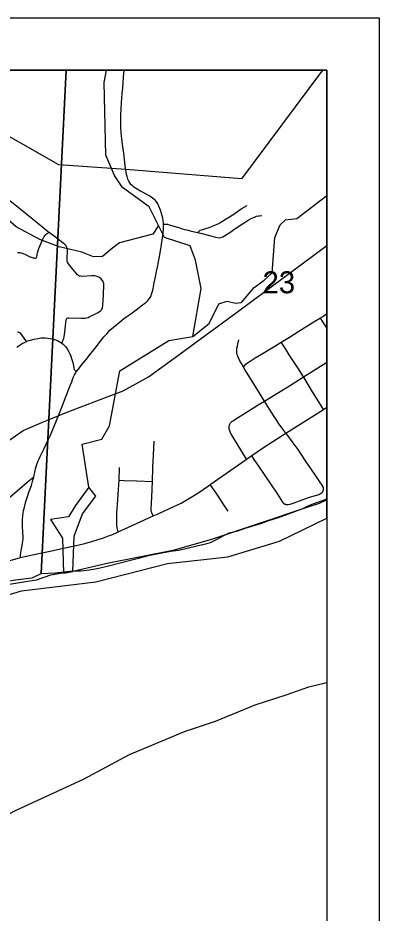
# Model space of a CAD drawing. Extents: x 0 to 34, y 0 to 22.
# Drawn here: x 8.311 to 9, y 19.29 to 21 of the extents above; entities that cross this region are included whole.
import ezdxf

# ---------------------------------------------------------------- set-up
doc = ezdxf.new("R2010")
doc.units = 0
for name, color, linetype in [('Default', 7, 'Continuous'), ('GM_X_City_Street', 7, 'Continuous'), ('GM_X_County_Road', 7, 'Continuous'), ('GM_X_Major_River', 7, 'Continuous'), ('GM_X_Minor_River', 7, 'Continuous'), ('GM_X_Rail_Line', 7, 'Continuous'), ('GM_X_Section_Text', 7, 'Continuous'), ('GM_X_State_Route', 7, 'Continuous'), ('SH_Data', 7, 'Continuous'), ('SH_Text', 7, 'Continuous')]:
    doc.layers.add(name, color=color, linetype=linetype)

msp = doc.modelspace()

# ---------------------------------------------------------------- linework, layer by layer
at = {"layer": 'Default'}
for points in [[(6.9494, 18.7612), (7.0197, 18.8208), (7.0624, 18.8705), (7.2079, 18.9977), (7.3928, 19.1502), (7.4623, 19.2086), (7.6025, 19.305), (7.8528, 19.4948), (7.9095, 19.5426), (8.0081, 19.6871), (8.1321, 19.8131), (8.2273, 19.878), (8.3177, 19.9057), (8.4594, 19.9228), (8.5959, 19.9577), (8.7115, 19.9703), (8.8098, 20.0002), (8.9, 20.0446), (8.9, 20.9), (6.3032, 20.9)], [(8.2273, 19.878), (8.3177, 19.9057), (8.4594, 19.9228), (8.5959, 19.9577), (8.7115, 19.9703), (8.8098, 20.0002), (8.9, 20.0446), (8.9, 20.9), (8.8919, 20.9), (8.7373, 20.6926), (8.5164, 20.7102), (8.3888, 20.7195), (8.089, 20.8898)]]:
    msp.add_lwpolyline(points, dxfattribs=at)
for points in [[(8.4029, 20.9), (7.3433, 20.9), (7.2788, 19.9659), (8.2644, 19.9182), (8.275, 19.9201), (8.2864, 19.9232), (8.3061, 19.9266), (8.3212, 19.9286), (8.3379, 19.9305), (8.3553, 19.9386)], [(8.9, 20.0813), (8.9, 20.9), (8.4029, 20.9), (8.3553, 19.9386), (8.3822, 19.9402), (8.4094, 19.9433), (8.417, 19.9437), (8.4307, 19.9438), (8.4424, 19.9453), (8.4549, 19.9469), (8.4678, 19.9492), (8.4833, 19.9534), (8.5283, 19.9646), (8.5408, 19.968), (8.5624, 19.9738), (8.5791, 19.9772), (8.6022, 19.9811), (8.6173, 19.983), (8.6313, 19.9865), (8.6544, 19.9923), (8.6692, 19.9954), (8.6783, 19.998), (8.6911, 20.0045), (8.7036, 20.011), (8.7138, 20.0164), (8.7301, 20.0202), (8.7445, 20.0252), (8.757, 20.0294), (8.7759, 20.0348), (8.7895, 20.0401), (8.8062, 20.0451), (8.8221, 20.0505), (8.8391, 20.0573), (8.8531, 20.0623), (8.866, 20.0688), (8.8743, 20.0718), (8.8917, 20.078)]]:
    msp.add_lwpolyline(points, close=True, dxfattribs=at)
at = {"layer": 'GM_X_City_Street'}
for points in [[(8.2922, 20.6538), (8.3205, 20.6311), (8.328, 20.625), (8.3583, 20.6004), (8.3661, 20.5938), (8.3704, 20.5902)], [(8.6536, 20.5899), (8.6559, 20.5923), (8.6573, 20.5935), (8.6587, 20.5943), (8.6608, 20.5952), (8.6635, 20.5961), (8.6676, 20.5973), (8.6757, 20.5999), (8.682, 20.6023), (8.6878, 20.6047), (8.6939, 20.6075), (8.6997, 20.6108), (8.7227, 20.6253), (8.737, 20.6351), (8.7426, 20.6385), (8.7481, 20.6418)], [(8.5887, 20.606), (8.5911, 20.606), (8.593, 20.606), (8.5964, 20.6057), (8.5996, 20.6048), (8.6153, 20.6), (8.6194, 20.5987), (8.6241, 20.5973), (8.6289, 20.5959), (8.6331, 20.5949), (8.6396, 20.5933), (8.6536, 20.5899), (8.6568, 20.5892), (8.6618, 20.5879), (8.6791, 20.5835), (8.6875, 20.5812), (8.6916, 20.5804), (8.6946, 20.5802), (8.6976, 20.5804), (8.6998, 20.581), (8.702, 20.5818), (8.7052, 20.5835), (8.7119, 20.5879), (8.717, 20.5915), (8.7225, 20.5955), (8.7267, 20.5982), (8.7391, 20.6065), (8.7502, 20.6135), (8.7573, 20.6174), (8.7619, 20.6195), (8.766, 20.621), (8.7698, 20.6219), (8.7717, 20.6221), (8.7763, 20.6224)], [(8.3099, 20.5521), (8.3121, 20.552), (8.3144, 20.5517), (8.3165, 20.5513), (8.3193, 20.5503), (8.3279, 20.5466), (8.3324, 20.5445), (8.3381, 20.5423), (8.3397, 20.5417), (8.3411, 20.5414), (8.3428, 20.5411), (8.3443, 20.5412), (8.3453, 20.5416), (8.3461, 20.5423), (8.3466, 20.5437), (8.3471, 20.5463), (8.3476, 20.5488), (8.3481, 20.5513), (8.3508, 20.5596), (8.3544, 20.5683), (8.3572, 20.575), (8.3596, 20.5802), (8.361, 20.5827), (8.3626, 20.5847), (8.3638, 20.586), (8.3653, 20.5873), (8.3672, 20.5885), (8.3704, 20.5902)], [(8.3946, 20.3787), (8.3953, 20.3804), (8.3972, 20.3846), (8.3985, 20.3884), (8.399, 20.3907), (8.4, 20.3994), (8.4029, 20.4234), (8.4035, 20.4248), (8.4041, 20.4256), (8.4052, 20.4266), (8.4063, 20.4269), (8.4076, 20.4271), (8.4312, 20.4264), (8.4361, 20.4264), (8.4392, 20.4264), (8.4417, 20.4268), (8.4446, 20.4277), (8.4468, 20.4287), (8.4575, 20.4342), (8.464, 20.4374), (8.468, 20.4402), (8.47, 20.4422), (8.4711, 20.4438), (8.4719, 20.4454), (8.4723, 20.4471), (8.4728, 20.4494), (8.473, 20.4528), (8.4733, 20.4586), (8.4738, 20.4724), (8.4741, 20.4768), (8.4746, 20.4848), (8.4746, 20.4879), (8.4744, 20.492), (8.4739, 20.4942), (8.4731, 20.4965), (8.4719, 20.4984), (8.4694, 20.5014), (8.4673, 20.5033), (8.4653, 20.5047), (8.4632, 20.5056), (8.4598, 20.5065), (8.457, 20.507), (8.4515, 20.5071), (8.4332, 20.5061), (8.4302, 20.5064), (8.4283, 20.5068), (8.4272, 20.5074), (8.4257, 20.5084), (8.4244, 20.5095), (8.4214, 20.513), (8.415, 20.5206), (8.41, 20.5268), (8.4073, 20.5305), (8.4055, 20.5334), (8.4049, 20.5346), (8.4046, 20.5361), (8.4049, 20.5435), (8.4052, 20.5528), (8.405, 20.5578), (8.4048, 20.5595), (8.4043, 20.5618), (8.4037, 20.5632), (8.4025, 20.5649), (8.4016, 20.566), (8.4003, 20.5672), (8.3972, 20.5698), (8.3882, 20.5768), (8.3848, 20.5795), (8.3756, 20.5863), (8.3704, 20.5902)], [(8.7411, 20.3331), (8.7438, 20.3362), (8.745, 20.3377), (8.7459, 20.3386), (8.7487, 20.3409), (8.7537, 20.3444), (8.7637, 20.3506), (8.7753, 20.3575), (8.8009, 20.3728), (8.8134, 20.3803), (8.8291, 20.3903), (8.8469, 20.4016), (8.8772, 20.4206), (8.888, 20.4272), (8.8924, 20.4299), (8.8997, 20.4345), (8.9, 20.4347)], [(8.9, 20.4078), (8.8929, 20.4192), (8.888, 20.4272)], [(8.3085, 20.3706), (8.3113, 20.3729), (8.319, 20.3779), (8.3231, 20.3802), (8.3274, 20.3821), (8.329, 20.3829), (8.3347, 20.3847), (8.3414, 20.3865), (8.3488, 20.3879), (8.3547, 20.3886), (8.3585, 20.3888), (8.3624, 20.3887), (8.3675, 20.3882), (8.372, 20.3875), (8.3784, 20.3862), (8.3822, 20.3851), (8.3859, 20.3836), (8.3895, 20.3818), (8.3928, 20.38), (8.3946, 20.3787), (8.3972, 20.3767), (8.3996, 20.3743), (8.4022, 20.3715), (8.4046, 20.3681), (8.4073, 20.3633), (8.4099, 20.3584), (8.4117, 20.3538), (8.4132, 20.3494), (8.4153, 20.3419), (8.4167, 20.3352), (8.4175, 20.3309), (8.4182, 20.3284), (8.419, 20.327), (8.4203, 20.3257), (8.4221, 20.3237)], [(8.3274, 20.3821), (8.326, 20.3839), (8.316, 20.397), (8.3141, 20.3985), (8.3124, 20.3993), (8.3113, 20.3996), (8.31, 20.3998)], [(8.7411, 20.3331), (8.7373, 20.3401), (8.7339, 20.3464), (8.7312, 20.3517), (8.7303, 20.3536), (8.7298, 20.3551), (8.7293, 20.3565), (8.729, 20.3581), (8.7287, 20.3598), (8.7285, 20.3618), (8.7284, 20.3637), (8.7284, 20.3655), (8.7288, 20.3693), (8.7295, 20.3731), (8.7302, 20.3766), (8.7321, 20.385)], [(8.8938, 20.2521), (8.8881, 20.2613), (8.8731, 20.2855), (8.858, 20.3105), (8.8556, 20.3143), (8.8448, 20.3315), (8.8286, 20.3565), (8.8219, 20.3669), (8.8134, 20.3803)], [(8.7138, 20.2202), (8.7143, 20.2221), (8.7151, 20.224), (8.7165, 20.2262), (8.7183, 20.2281), (8.7197, 20.2295), (8.7214, 20.2306), (8.7244, 20.2326), (8.7449, 20.2456), (8.7532, 20.251), (8.7692, 20.2607), (8.7811, 20.268), (8.8051, 20.2828), (8.829, 20.2973), (8.8556, 20.3143), (8.8688, 20.3227), (8.9, 20.3425)], [(8.8939, 20.0987), (8.8941, 20.1005), (8.894, 20.1018), (8.8936, 20.103), (8.8931, 20.1041), (8.8913, 20.1073), (8.8872, 20.1136), (8.878, 20.1269), (8.8594, 20.1541), (8.8455, 20.1755), (8.8401, 20.1831), (8.8341, 20.191), (8.8257, 20.2023), (8.8223, 20.2067), (8.8179, 20.2116), (8.8091, 20.224), (8.7939, 20.2475), (8.7811, 20.268), (8.7711, 20.2843), (8.7642, 20.2958), (8.7439, 20.3285), (8.7411, 20.3331)], [(8.7467, 20.1569), (8.741, 20.1664), (8.7191, 20.2031), (8.7167, 20.2075), (8.7149, 20.2115), (8.7139, 20.2146), (8.7136, 20.2165), (8.7136, 20.2179), (8.7137, 20.2192), (8.7138, 20.2202)], [(8.5689, 20.0487), (8.5664, 20.0546), (8.5656, 20.0569), (8.5652, 20.0587), (8.5652, 20.0618), (8.5664, 20.0848), (8.5675, 20.1146), (8.5682, 20.1413), (8.5693, 20.1649), (8.5706, 20.1917)], [(8.8221, 20.0702), (8.8202, 20.0707), (8.819, 20.0715), (8.818, 20.0727), (8.8166, 20.0748), (8.8066, 20.0904), (8.7827, 20.126), (8.7708, 20.1434), (8.7618, 20.1567), (8.757, 20.1639)], [(8.5019, 20.0184), (8.5002, 20.0262), (8.4997, 20.0319), (8.4995, 20.0412), (8.4997, 20.0549), (8.5007, 20.0704), (8.5028, 20.0989), (8.5039, 20.1169), (8.5047, 20.1413)], [(8.0831, 19.9074), (8.1015, 19.9229), (8.1196, 19.938), (8.1364, 19.9522), (8.1758, 19.9853), (8.2242, 20.0256), (8.2649, 20.0597), (8.2994, 20.0885), (8.3284, 20.1129), (8.3412, 20.1236)], [(8.5039, 20.1169), (8.5134, 20.1166), (8.5375, 20.1159), (8.5675, 20.1146)], [(8.712, 20.0577), (8.7026, 20.0719), (8.6949, 20.0837), (8.6871, 20.0951), (8.6836, 20.1002), (8.6779, 20.1089)], [(8.8221, 20.0702), (8.8259, 20.0704), (8.8302, 20.0714), (8.8379, 20.0738), (8.8553, 20.0802), (8.8654, 20.0836), (8.8849, 20.0899), (8.8883, 20.0914), (8.8903, 20.0928), (8.8917, 20.0941), (8.8927, 20.0956), (8.8934, 20.0973), (8.8939, 20.0987)]]:
    msp.add_lwpolyline(points, dxfattribs=at)
at = {"layer": 'GM_X_County_Road'}
for points in [[(8.5166, 20.7097), (8.5163, 20.712), (8.5127, 20.7416), (8.5105, 20.7581), (8.5089, 20.7698), (8.508, 20.7797), (8.5073, 20.7915), (8.507, 20.8021), (8.5069, 20.8076), (8.5069, 20.8095), (8.5069, 20.8143), (8.5075, 20.8261), (8.5083, 20.8379), (8.5098, 20.8558), (8.5106, 20.8662), (8.5114, 20.8761), (8.5124, 20.8864), (8.513, 20.8944), (8.5136, 20.9)], [(8.3159, 19.9691), (8.3158, 19.9746), (8.3163, 19.9782), (8.3167, 19.9818), (8.3195, 19.9957), (8.3203, 20.0009), (8.3205, 20.0036), (8.3206, 20.006), (8.3205, 20.0109), (8.3202, 20.0153), (8.3201, 20.0183), (8.32, 20.0211), (8.3197, 20.0259), (8.3194, 20.0339), (8.3194, 20.0413), (8.32, 20.0489), (8.3205, 20.0541), (8.3214, 20.0589), (8.3223, 20.0629), (8.3259, 20.0761), (8.3287, 20.0857), (8.3317, 20.0939), (8.3363, 20.107), (8.3388, 20.1144), (8.3412, 20.1236), (8.3451, 20.1411), (8.3462, 20.1452), (8.3473, 20.1487), (8.3489, 20.1526), (8.3511, 20.1576), (8.3531, 20.162), (8.3609, 20.1777), (8.3655, 20.1871), (8.3687, 20.1937), (8.3728, 20.2032), (8.3765, 20.2123), (8.3829, 20.2275), (8.39, 20.2449), (8.3957, 20.2594), (8.4028, 20.2779), (8.4083, 20.2925), (8.4109, 20.2989), (8.4133, 20.3049), (8.4149, 20.3091), (8.4168, 20.3144), (8.4184, 20.3179), (8.4203, 20.3212), (8.4221, 20.3237), (8.4256, 20.3282), (8.4341, 20.3389), (8.4414, 20.3482), (8.445, 20.3525), (8.4579, 20.3691), (8.4702, 20.3848), (8.4749, 20.3906), (8.4801, 20.3968), (8.4834, 20.4006), (8.4864, 20.4037), (8.493, 20.4095), (8.4998, 20.415), (8.5032, 20.4177), (8.5125, 20.4249), (8.5185, 20.4294), (8.5241, 20.4333), (8.5286, 20.4366), (8.5361, 20.4422), (8.542, 20.4466), (8.5486, 20.4517), (8.5524, 20.4545), (8.5555, 20.4572), (8.5586, 20.4602), (8.5617, 20.4639), (8.5641, 20.4681), (8.5658, 20.472), (8.5671, 20.476), (8.5687, 20.4826), (8.571, 20.4941), (8.5731, 20.5051), (8.5752, 20.5155), (8.5769, 20.524), (8.581, 20.544), (8.5831, 20.555), (8.5843, 20.563), (8.5856, 20.5719), (8.5866, 20.5796), (8.5877, 20.588), (8.5886, 20.5978), (8.5888, 20.5996), (8.5888, 20.6026), (8.5887, 20.606), (8.5885, 20.6084), (8.5879, 20.6126), (8.587, 20.6174), (8.5858, 20.6222), (8.5846, 20.6263), (8.5825, 20.6327), (8.5797, 20.6401), (8.5774, 20.645), (8.5756, 20.6481), (8.5733, 20.6509), (8.5707, 20.6533), (8.5669, 20.6564), (8.5622, 20.6594), (8.5553, 20.6634), (8.5498, 20.6663), (8.5432, 20.6698), (8.5384, 20.6726), (8.5351, 20.6745), (8.532, 20.6767), (8.5291, 20.6791), (8.5264, 20.682), (8.5242, 20.685), (8.5222, 20.6883), (8.5207, 20.6918), (8.5197, 20.6943), (8.5189, 20.6972), (8.518, 20.7008), (8.5171, 20.7058), (8.5166, 20.7097)]]:
    msp.add_lwpolyline(points, dxfattribs=at)
at = {"layer": 'GM_X_Major_River'}
msp.add_line((8.4155, 19.9425), (8.3728, 19.9358), dxfattribs=at)
for points in [[(8.9, 20.0792), (8.8856, 20.0727), (8.8618, 20.065), (8.6802, 20.0039), (8.6066, 19.9824), (8.4812, 19.9575), (8.4155, 19.9425)], [(8.3728, 19.9358), (8.3456, 19.9259), (8.2425, 19.9091), (8.2002, 19.8972), (8.1417, 19.865), (8.0633, 19.804), (8.0019, 19.7441), (7.9196, 19.636), (7.8409, 19.5529), (7.8311, 19.546), (7.807, 19.5171), (7.7479, 19.4607), (7.6691, 19.4087), (7.6318, 19.3809), (7.5765, 19.3237), (7.5633, 19.3153), (7.5402, 19.3141), (7.5263, 19.3091), (7.5157, 19.2992), (7.5007, 19.2748)], [(7.8827, 19.235), (7.9818, 19.3041), (8.07, 19.358), (8.1666, 19.415), (8.262, 19.4632), (8.3058, 19.4861), (8.4356, 19.5459), (8.5238, 19.5929), (8.6288, 19.6366), (8.688, 19.6566), (8.7635, 19.6877), (8.8228, 19.7069), (8.8658, 19.7223), (8.9, 19.7307)]]:
    msp.add_lwpolyline(points, dxfattribs=at)
at = {"layer": 'GM_X_Minor_River'}
for points in [[(8.5788, 20.6036), (8.568, 20.5866), (8.5043, 20.5702), (8.4884, 20.5584), (8.4721, 20.5443), (8.4551, 20.5439), (8.4327, 20.5527), (8.3891, 20.5629), (8.3527, 20.5769), (8.3072, 20.6012), (8.2758, 20.6281), (8.2557, 20.646), (8.2299, 20.6619), (8.1845, 20.7018), (8.131, 20.7261), (8.1106, 20.7477), (8.1091, 20.7625), (8.1098, 20.7675), (8.1182, 20.8105), (8.1129, 20.8295), (8.1, 20.8564), (8.0803, 20.9)], [(8.4463, 20.1034), (8.433, 20.186), (8.4709, 20.1954), (8.4853, 20.221), (8.5052, 20.3259), (8.5986, 20.3837), (8.6444, 20.3917), (8.6607, 20.4833), (8.6493, 20.5375), (8.6395, 20.5643), (8.5903, 20.5806), (8.5611, 20.6392), (8.5101, 20.6759), (8.495, 20.6989), (8.4785, 20.7379), (8.4752, 20.8764), (8.4797, 20.9)], [(8.6444, 20.3917), (8.676, 20.4161), (8.6942, 20.4537), (8.7101, 20.4591), (8.7257, 20.4549), (8.7374, 20.4561), (8.7617, 20.485), (8.7806, 20.4991), (8.7962, 20.5128), (8.8008, 20.5804), (8.811, 20.6048), (8.8212, 20.6143), (8.8428, 20.617), (8.9, 20.6609)], [(8.4463, 20.1034), (8.4205, 20.0686), (8.4072, 20.0472), (8.3731, 20.0416), (8.3956, 20.0061), (8.3975, 19.9395)], [(8.4155, 19.9425), (8.4179, 20.0102), (8.4337, 20.0524), (8.4594, 20.0864), (8.4463, 20.1034)], [(8.3975, 19.9395), (8.4155, 19.9425)]]:
    msp.add_lwpolyline(points, dxfattribs=at)
at = {"layer": 'GM_X_Rail_Line'}
msp.add_lwpolyline([(8.2404, 20.1565), (8.3206, 20.2117), (8.3566, 20.2273), (8.4027, 20.2461), (8.4698, 20.2716), (8.5115, 20.2877), (8.5597, 20.3141), (8.6108, 20.3511), (8.732, 20.4407), (8.9, 20.5652)], dxfattribs=at)
at = {"layer": 'GM_X_State_Route'}
for points in [[(8.4835, 20.0104), (8.4881, 20.0122), (8.4969, 20.0159), (8.5019, 20.0184), (8.5216, 20.027), (8.5689, 20.0487), (8.5785, 20.0527), (8.6014, 20.0632), (8.6224, 20.0733), (8.6383, 20.0823), (8.6538, 20.0921), (8.6742, 20.1063), (8.6779, 20.1089), (8.746, 20.1564), (8.7467, 20.1569), (8.757, 20.1639), (8.7777, 20.178), (8.8058, 20.1964), (8.8223, 20.2067), (8.8718, 20.2377), (8.8938, 20.2521), (8.9, 20.2562)], [(8.3754, 19.9823), (8.389, 19.9853), (8.4217, 19.9924), (8.4385, 19.9963), (8.4535, 20.0003), (8.4743, 20.0068), (8.4835, 20.0104)], [(8.0831, 19.9074), (8.092, 19.8974), (8.1035, 19.8835), (8.1112, 19.8743), (8.1202, 19.8807), (8.1388, 19.8931), (8.1525, 19.9018), (8.1654, 19.9093), (8.1835, 19.9191), (8.1973, 19.9262), (8.2114, 19.9329), (8.2268, 19.9396), (8.2464, 19.9476), (8.2616, 19.9532), (8.2788, 19.9588), (8.2913, 19.9626), (8.3004, 19.965), (8.3159, 19.9691), (8.3356, 19.9736), (8.3754, 19.9823)]]:
    msp.add_lwpolyline(points, dxfattribs=at)
at = {"layer": 'SH_Data'}
for p, q in [((2, 21), (9, 21)), ((9, 21), (9, 14)), ((2.1, 20.9), (8.9, 20.9)), ((8.9, 20.9), (8.9, 14.1))]:
    msp.add_line(p, q, dxfattribs=at)
at = {"layer": 'SH_Text'}
msp.add_lwpolyline([(6.9494, 18.7612), (7.0197, 18.8208), (7.0624, 18.8705), (7.2079, 18.9977), (7.3928, 19.1502), (7.4623, 19.2086), (7.6025, 19.305), (7.8528, 19.4948), (7.9095, 19.5426), (8.0081, 19.6871), (8.1321, 19.8131), (8.2273, 19.878), (8.3177, 19.9057), (8.4594, 19.9228), (8.5959, 19.9577), (8.7115, 19.9703), (8.8098, 20.0002), (8.9, 20.0446), (8.9, 20.9), (2.1, 20.9)], dxfattribs=at)

# ---------------------------------------------------------------- texts
at = {"layer": 'GM_X_Section_Text'}
msp.add_text('23', height=0.04186, rotation=0, dxfattribs=at).set_placement((8.7775, 20.474))

doc.saveas('drawing.dxf')
